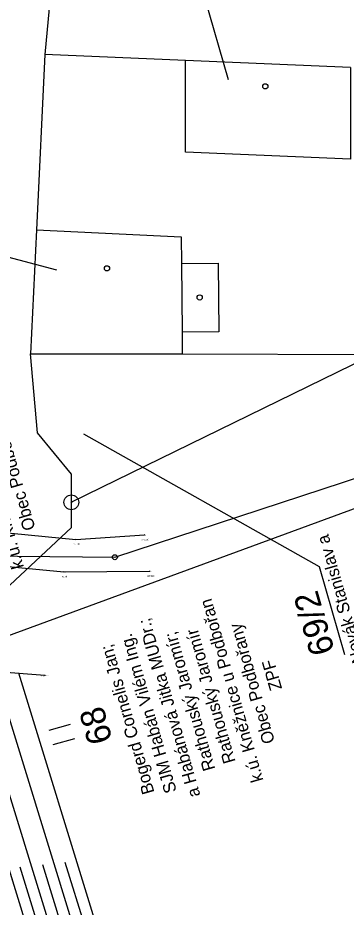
# Model space of a CAD drawing. Extents: x -809973 to -809318, y -1011363 to -1010505.
# Drawn here: x -809813.5 to -809791.5, y -1011009.4 to -1010949.7 of the extents above; entities that cross this region are included whole.
import ezdxf

# ---------------------------------------------------------------- set-up
doc = ezdxf.new("R2010")
doc.units = 0
for name, color, linetype in [('18b - zaměření - čísla bodů', 7, 'Continuous'), ('18c - zaměření - výšky', 7, 'Continuous'), ('19a - katastr hranice', 7, 'Continuous'), ('19c - katastr popisy', 7, 'Continuous'), ('21d - sítě - obnova rybníku a obnova náhonu pro rybník', 7, 'Continuous'), ('stav_stav', 7, 'Continuous')]:
    doc.layers.add(name, color=color, linetype=linetype)

# ---------------------------------------------------------------- blocks, each defined once
blk = doc.blocks.new('POINT_DISPLAY')
for p, q in [((-0.021, -0.021), (0.021, 0.021)), ((-0.021, 0.021), (0.021, -0.021))]:
    blk.add_line(p, q)

msp = doc.modelspace()

# ---------------------------------------------------------------- linework, layer by layer
at = {"layer": '19a - katastr hranice'}
for p, q in [((-809810.23, -1010936.6), (-809811.73, -1010952.15)), ((-809802.28, -1010952.55), (-809811.73, -1010952.15)), ((-809791.19, -1010953.02), (-809802.28, -1010952.55)), ((-809812.29, -1010963.93), (-809802.55, -1010964.39)), ((-809802.55, -1010964.39), (-809802.54, -1010966.18)), ((-809802.54, -1010966.18), (-809800.07, -1010966.17)), ((-809802.54, -1010966.18), (-809802.5, -1010970.8)), ((-809800.07, -1010966.17), (-809800.04, -1010970.79)), ((-809800.04, -1010970.79), (-809802.5, -1010970.8)), ((-809802.5, -1010970.8), (-809802.49, -1010972.27)), ((-809789.65, -1010972.3), (-809809.94, -1010982.24)), ((-809782.36, -1010979.51), (-809823.59, -1010994.66))]:
    msp.add_line(p, q, dxfattribs=at)
for points in [[(-809811.73, -1010952.15), (-809812.29, -1010963.93), (-809812.69, -1010972.27)], [(-809791.19, -1010953.02), (-809791.19, -1010959.17), (-809802.28, -1010958.7), (-809802.28, -1010952.55)], [(-809812.69, -1010972.27), (-809802.49, -1010972.27), (-809789.65, -1010972.3)], [(-809809.94, -1010982.24), (-809809.94, -1010980.34), (-809812.22, -1010977.58), (-809812.69, -1010972.27)], [(-809825.08, -1010988.69), (-809814.76, -1010988.43), (-809809.94, -1010983.94), (-809809.94, -1010982.24)]]:
    msp.add_lwpolyline(points, dxfattribs=at)
for radius in [0.5, 0.0303]:
    msp.add_circle((-809809.94, -1010982.24), radius, dxfattribs=at)
at = {"layer": '19c - katastr popisy'}
for p, q in [((-809802.958, -1010941.417), (-809799.403, -1010953.831)), ((-809826.435, -1010962.52), (-809810.927, -1010966.61)), ((-809793.256, -1010986.574), (-809809.11, -1010977.649)), ((-809791.559, -1010992.497), (-809793.256, -1010986.574)), ((-809810.011, -1010997.163), (-809811.453, -1010997.576)), ((-809809.736, -1010998.126), (-809811.178, -1010998.539))]:
    msp.add_line(p, q, dxfattribs=at)
for centre in [(-809796.907, -1010954.289), (-809796.907, -1010954.289), (-809807.547, -1010966.519), (-809807.547, -1010966.519), (-809801.317, -1010968.469), (-809801.317, -1010968.469)]:
    msp.add_circle(centre, 0.175, dxfattribs=at)
at = {"layer": '21d - sítě - obnova rybníku a obnova náhonu pro rybník'}
msp.add_lwpolyline([(-809884.652, -1011011.671), (-809852.391, -1010992.741), (-809838.71, -1010989.006), (-809826.649, -1010985.714), (-809807.016, -1010985.926), (-809784.688, -1010978.607)], dxfattribs=at)
msp.add_circle((-809807.016, -1010985.926), 0.169, dxfattribs=at)
at = {"layer": 'stav_stav'}
for p, q in [((-809817.51, -1010983.979), (-809809.643, -1010984.731)), ((-809809.643, -1010984.731), (-809805.029, -1010984.43)), ((-809817.539, -1010986.227), (-809810.453, -1010986.917)), ((-809810.453, -1010986.917), (-809804.657, -1010986.868)), ((-809822.313, -1010992.998), (-809811.732, -1010993.858)), ((-809809.99, -1011020.331), (-809818.307, -1010993.324)), ((-809808.556, -1011019.89), (-809816.697, -1010993.454)), ((-809807.123, -1011019.448), (-809815.087, -1010993.585)), ((-809805.689, -1011019.007), (-809813.478, -1010993.716)), ((-809807.839, -1011019.669), (-809811.866, -1011006.594)), ((-809806.406, -1011019.228), (-809810.344, -1011006.439)), ((-809809.273, -1011020.11), (-809813.388, -1011006.75))]:
    msp.add_line(p, q, dxfattribs=at)

# ---------------------------------------------------------------- block references
at = {"layer": '18b - zaměření - čísla bodů'}
for p in [(-809805.029, -1010984.43), (-809809.643, -1010984.731), (-809810.453, -1010986.917), (-809804.657, -1010986.868), (-809811.732, -1010993.858)]:
    msp.add_blockref('POINT_DISPLAY', p, dxfattribs=at)

# ---------------------------------------------------------------- texts
for s, p in [('5090', (-809805.029, -1010984.48)), ('5089', (-809809.643, -1010984.781)), ('5088', (-809810.453, -1010986.967)), ('5091', (-809804.657, -1010986.918)), ('5104', (-809811.732, -1010993.908))]:
    msp.add_text(s, height=0.05, dxfattribs=at).set_placement(p)
at = {"layer": '18c - zaměření - výšky'}
for s, p in [('245.388', (-809809.846, -1010985.094)), ('245.319', (-809805.232, -1010984.793)), ('245.501', (-809810.648, -1010987.28)), ('245.446', (-809804.86, -1010987.231)), ('246.464', (-809811.964, -1010993.941))]:
    msp.add_text(s, height=0.1, dxfattribs=at).set_placement(p)
at = {"layer": '19c - katastr popisy'}
for s, height, p in [('k.ú. Kněžnice u Podbořan', 0.83338, (-809813.115, -1010986.586)), ('Obec Podbořany', 0.83338, (-809812.343, -1010984)), ('SJM Novák Stanislav a', 0.83338, (-809789.524, -1010995.357)), ('69/2', 1.6667, (-809792.23, -1010992.243)), ('k.ú. Kněžnice u Podbořan', 0.83338, (-809797.028, -1011000.917)), ('a Habánová Jitka MUDr.;', 0.83338, (-809801.26, -1011001.928)), ('Obec Podbořany', 0.83338, (-809796.256, -1010998.331)), ('SJM Habán Vilém Ing.', 0.83338, (-809802.852, -1011001.65)), ('Rathouský Jaromír;', 0.83338, (-809800.261, -1011000.153)), ('Rathouský Jaromír', 0.83338, (-809798.896, -1010999.656)), ('Bogerd Cornelis Jan;', 0.83338, (-809804.348, -1011001.725)), ('ZPF', 0.8334, (-809795.771, -1010994.752)), ('68', 1.6667, (-809807.154, -1010998.223))]:
    msp.add_text(s, height=height, rotation=105.98192, dxfattribs=at).set_placement(p)

doc.saveas('drawing.dxf')
